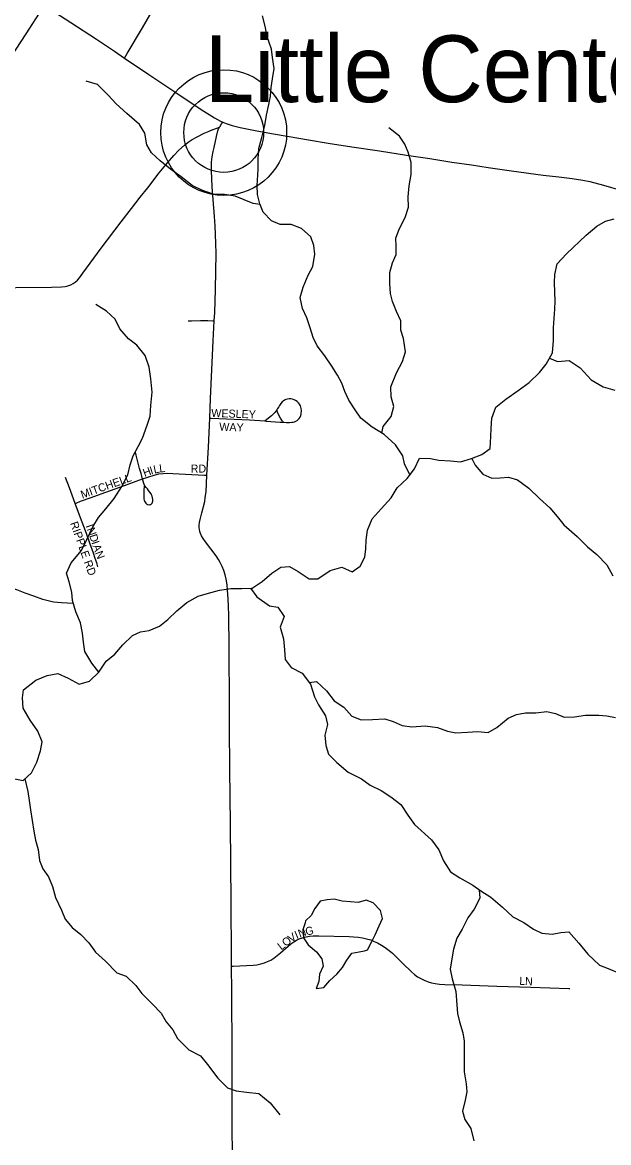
# Model space of a CAD drawing. Extents: x 1442749 to 1756758, y 235267 to 677782.
# Drawn here: x 1580655 to 1584314, y 536473 to 543469 of the extents above; entities that cross this region are included whole.
import ezdxf

# ---------------------------------------------------------------- set-up
doc = ezdxf.new("R2010")
doc.units = 0
for name, color, linetype in [('GM_X_County_Road', 7, 'Continuous'), ('GM_X_Major_River', 7, 'Continuous'), ('GM_X_Minor_Lake', 7, 'Continuous'), ('GM_X_Minor_River', 7, 'Continuous'), ('GM_X_Township_Road', 7, 'Continuous'), ('GM_X_Township_Subdivision', 7, 'Continuous'), ('GM_X_Township_Subdivision_Text', 7, 'Continuous'), ('GM_X_Unincorporated', 7, 'Continuous'), ('GM_X_Unincorporated_Location', 7, 'Continuous'), ('GM_X_Unincorporated_Text', 7, 'Continuous')]:
    doc.layers.add(name, color=color, linetype=linetype)

msp = doc.modelspace()

# ---------------------------------------------------------------- linework, layer by layer
at = {"layer": 'GM_X_County_Road'}
for points in [[(1580791.7, 543575.1), (1580957.8, 543468.8), (1581117.1, 543364.6), (1581228.7, 543289.4), (1581291.8, 543246.9)], [(1581291.8, 543246.9), (1581308.4, 543274.6), (1581404.2, 543435.1), (1581504.9, 543608)], [(1581291.8, 543246.9), (1581443.6, 543144.6), (1581607, 543034.9), (1581771, 542926), (1581854.2, 542874), (1581891.1, 542853.3), (1581905.4, 542846.9)], [(1581905.4, 542846.9), (1581926.5, 542837.5), (1581963.3, 542824.9), (1582013.8, 542812), (1582106.8, 542793.2), (1582210.2, 542775.2), (1582320.2, 542757.2), (1582439.8, 542736.8), (1582562.6, 542715.4), (1582711.6, 542692.3), (1582883.6, 542666.8), (1583052.4, 542640.8), (1583198.2, 542618.8), (1583334.3, 542597.3), (1583457.5, 542578.8), (1583561.3, 542563.4), (1583707.3, 542543.1), (1583905.2, 542515.7), (1584002.7, 542503.9), (1584087.3, 542495.1), (1584152.1, 542485), (1584197.1, 542475.4), (1584282.8, 542452.7), (1584396.1, 542419.2)]]:
    msp.add_lwpolyline(points, dxfattribs=at)
at = {"layer": 'GM_X_Major_River'}
msp.add_lwpolyline([(1580606.3, 538744.2), (1580658.3, 538735.1), (1580711.4, 538782.1), (1580744.9, 538849.7), (1580768.5, 538919.4), (1580777.8, 538975.4), (1580751.2, 539042.2), (1580702.6, 539111.5), (1580660.1, 539186.6), (1580655.5, 539251), (1580660.6, 539301), (1580738.1, 539361.6), (1580808.9, 539390.2), (1580875.3, 539402.9), (1580940.8, 539373.4), (1581008.1, 539335.9), (1581072.7, 539354.6), (1581132, 539411.5), (1581177.7, 539480.8), (1581230.7, 539523.8), (1581282.1, 539581), (1581341.5, 539639.9), (1581392.1, 539662.9), (1581446.4, 539671.8), (1581511.1, 539698.6), (1581562.1, 539739.7), (1581619.4, 539794.6), (1581680.7, 539845.5), (1581751.7, 539886.2), (1581816.3, 539904.9), (1581884.8, 539923.5), (1581955.2, 539934.1), (1582023.4, 539934.7), (1582089.5, 539935.3), (1582150.6, 539978.1), (1582211.8, 540029), (1582268.8, 540068), (1582321, 540070.9), (1582376.4, 540039.6), (1582445.5, 539994), (1582499.7, 539994.9), (1582574.9, 540045.5), (1582647.6, 540068), (1582713.1, 540038.5), (1582764, 540073.6), (1582791.2, 540129.2), (1582798.4, 540181.2), (1582799.6, 540235.4), (1582808.9, 540297.4), (1582838.6, 540369.1), (1582894.1, 540432.1), (1582955.7, 540499.1), (1582993.1, 540562.5), (1583056.5, 540621.4), (1583101.9, 540680.6), (1583133.5, 540748.2), (1583201.5, 540744.8), (1583253.5, 540735.7), (1583327.5, 540732.1), (1583389.5, 540724.8), (1583458.1, 540745.4), (1583522.8, 540770.1), (1583573.7, 540807.2), (1583579.4, 540883.3), (1583580.5, 540933.5), (1583585.9, 540997.6), (1583609.4, 541065.3), (1583672.7, 541116.2), (1583750, 541170.8), (1583817.2, 541219.5), (1583882.7, 541282.4), (1583924, 541335.7), (1583963.6, 541405.1), (1583969.3, 541483.3), (1583969, 541561.5), (1583974.3, 541619.6), (1583977.6, 541677.8), (1583980.7, 541727.9), (1583977.9, 541784.1), (1583975.2, 541844.4), (1583978.3, 541894.5), (1583993.8, 541962.4), (1584051.3, 542023.4), (1584174.1, 542141.3), (1584241.5, 542196), (1584294.2, 542227), (1584348.7, 542242)], dxfattribs=at)
at = {"layer": 'GM_X_Minor_Lake'}
for points in [[(1582789.4, 537671.6), (1582809.4, 537676), (1582836.1, 537729.8), (1582856.7, 537771.7), (1582881.4, 537827.5), (1582902, 537873.4), (1582890.6, 537923.7), (1582845, 537970.4), (1582801.1, 537986.9), (1582750.9, 537973.4), (1582702.8, 537976), (1582650.7, 537980.6), (1582600.8, 537993.2), (1582556.6, 537989.7), (1582514.4, 537980.2), (1582479.8, 537934.4), (1582457.2, 537890.6), (1582422.8, 537858.9), (1582418.7, 537845)], [(1582418.7, 537845), (1582406.1, 537802.9), (1582409.5, 537752.7), (1582439, 537708.3), (1582490.6, 537663.6), (1582524.2, 537621.1), (1582531.6, 537574.8), (1582509, 537525), (1582504.5, 537478.9), (1582487.9, 537435), (1582536.1, 537442.4), (1582574.7, 537486.1), (1582617.3, 537525.7), (1582653.8, 537567.4), (1582680.4, 537613.2), (1582711, 537657), (1582757.2, 537664.5), (1582789.4, 537671.6)]]:
    msp.add_lwpolyline(points, dxfattribs=at)
at = {"layer": 'GM_X_Minor_River'}
for points in [[(1583074, 540644.2), (1583040, 540711.7), (1583028.6, 540762), (1582983.3, 540830.7), (1582911.9, 540895.7), (1582838.3, 540940.7), (1582766.8, 540997.6), (1582731.4, 541050.2), (1582692, 541110.8), (1582666.6, 541163.3), (1582649.2, 541215.6), (1582621.7, 541266), (1582586.3, 541322.6), (1582543, 541387.3), (1582495.6, 541450), (1582470.2, 541502.4), (1582450.8, 541560.8), (1582429.5, 541623.2), (1582402.2, 541681.7), (1582389, 541752), (1582407.8, 541816), (1582438.7, 541889.9), (1582467.4, 541945.7), (1582480.4, 542021.8), (1582473, 542076), (1582455.6, 542130.3), (1582396.1, 542183.2), (1582332.3, 542207.9), (1582264.1, 542206.7), (1582210.3, 542229.4), (1582156.8, 542284.2), (1582137.4, 542336.5), (1582122, 542394.9), (1582120.7, 542451), (1582125.9, 542551.3), (1582126.7, 542615.4), (1582131.5, 542681.6), (1582148.3, 542749.6), (1582167.3, 542825.5), (1582178, 542889.6), (1582192.9, 542955.6), (1582203.5, 543009.7), (1582208.2, 543063.7), (1582216.8, 543117.8), (1582225.6, 543181.9), (1582216.4, 543250.2), (1582209, 543302.4), (1582179.9, 543384.9), (1582172.5, 543437.2), (1582153.4, 543509.6)], [(1582139.3, 542331.3), (1582095.3, 542339), (1581983.6, 542384.4), (1581915.6, 542395.2), (1581845.5, 542396), (1581775.6, 542420.9), (1581713.8, 542451.7), (1581646.3, 542504.6), (1581578.8, 542553.5), (1581515.2, 542604.4), (1581459.7, 542655.2), (1581432.3, 542705.6), (1581419.1, 542778), (1581385.7, 542832.5), (1581306.3, 542899.6), (1581238.9, 542960.5), (1581189.4, 543015.2), (1581124.1, 543082.2), (1581052.2, 543103)], [(1582898.4, 540903.9), (1582906.5, 540945.9), (1582957.3, 541007.5), (1582974.1, 541069.5), (1582956.8, 541129.8), (1582955.5, 541194), (1582990.7, 541279.9), (1583027.6, 541351.7), (1583046.3, 541411.6), (1583033.3, 541496), (1583015.9, 541546.3), (1583016.6, 541606.5), (1582989.2, 541662.9), (1582965.9, 541725.4), (1582952.5, 541775.7), (1582949.2, 541837.9), (1582948, 541908.1), (1582964.8, 541968.1), (1582987.4, 542020), (1582988.1, 542072.1), (1582986.6, 542122.2), (1583007.4, 542178.2), (1583044.3, 542251.9), (1583065.1, 542315.9), (1583061.9, 542380.1), (1583068.7, 542448.2), (1583081.6, 542520.2), (1583080.5, 542594.5), (1583063.2, 542658.8), (1583041.7, 542709.2), (1583008.3, 542759.8), (1582942.7, 542810.6)], [(1581131.4, 539410.9), (1581087, 539466.6), (1581043.8, 539541.3), (1581036.5, 539599.5), (1581029.2, 539655.8), (1581017.9, 539720.1), (1580988.7, 539788.6), (1580967.4, 539859.1), (1580962.1, 539911.3), (1580946.8, 539975.6), (1580929.4, 540030), (1580958.2, 540093.8), (1581023.3, 540171.3), (1581056.1, 540239.1), (1581095.2, 540318.9), (1581129.9, 540376.6), (1581174.7, 540430.3), (1581227.6, 540495.8), (1581274.6, 540571.5), (1581313.5, 540643.3), (1581328.3, 540705.3), (1581347, 540763.2), (1581377.7, 540821), (1581404.4, 540872.9), (1581433.5, 540954.8), (1581452.2, 541010.7), (1581457, 541076.8), (1581464, 541161), (1581456.9, 541243.3), (1581445.8, 541315.6), (1581420.6, 541388.1), (1581369.2, 541452.9), (1581317.6, 541493.6), (1581262.2, 541556.4), (1581232.9, 541614.9), (1581179.4, 541665.6), (1581113.7, 541708.5)], [(1583944.8, 541372.2), (1583995.6, 541350.6), (1584067.9, 541357.8), (1584135.5, 541310.9), (1584204.7, 541237.9), (1584280.4, 541192.9), (1584352.3, 541172)], [(1583460.4, 540746.3), (1583480.9, 540704.7), (1583528.3, 540648), (1583584.1, 540623.3), (1583636.2, 540624.7), (1583688.4, 540628.1), (1583744.3, 540613.4), (1583815.9, 540560.4), (1583883.2, 540495.5), (1583946.7, 540436.6), (1583992.1, 540383.9), (1584033.6, 540331.3), (1584116.9, 540258.2), (1584182.3, 540193.2), (1584239.8, 540146.4), (1584303.2, 540081.5), (1584340.5, 540012.9)], [(1580973, 539840.7), (1580899.1, 539843.8), (1580849.1, 539848.4), (1580783.1, 539865.2), (1580725.2, 539885.9), (1580671.4, 539904.6), (1580619.5, 539925.2), (1580553.6, 539948), (1580486.2, 540011), (1580464.8, 540061.4), (1580384.1, 540168)], [(1582078.7, 539935.2), (1582118.2, 539882), (1582197.7, 539824.9), (1582249.7, 539816.3), (1582289.1, 539759.7), (1582264.2, 539691.8), (1582285.4, 539619.3), (1582290.6, 539551.1), (1582293.9, 539490.9), (1582331.4, 539440.3), (1582401.1, 539405.4), (1582452.4, 539336.6), (1582477.5, 539258.1), (1582503, 539207.7), (1582546.3, 539139), (1582559.7, 539084.7), (1582542.8, 539016.7), (1582548, 538952.5), (1582565.4, 538898.1), (1582616.9, 538847.4), (1582688.4, 538786.4), (1582772.1, 538745.3), (1582825.7, 538704.6), (1582893.5, 538671.8), (1582955.1, 538632.9), (1583016.7, 538584.1), (1583060, 538517.4), (1583101.4, 538460.8), (1583208.5, 538363.3), (1583253.8, 538302.6), (1583283.1, 538232.1), (1583326.3, 538163.4), (1583386, 538126.6), (1583465.7, 538081.6), (1583517.3, 538044.9), (1583579, 538006.1), (1583652.4, 537943.1), (1583715.8, 537882.2), (1583785.6, 537847.3), (1583845.2, 537806.5), (1583897, 537781.8), (1583961.1, 537775.1), (1584015.3, 537784.5), (1584065.5, 537789.9), (1584128.8, 537719), (1584184.1, 537650.2), (1584257.4, 537581.1), (1584311.3, 537560.5), (1584379.1, 537531.6)], [(1582444.8, 539346.9), (1582490.7, 539352.2), (1582552.1, 539295.4), (1582601.5, 539232.7), (1582661.1, 539191.9), (1582710.6, 539137.1), (1582768.4, 539114.4), (1582840.6, 539115.6), (1582916.8, 539120.7), (1582968.7, 539104.1), (1583024.6, 539077.4), (1583086.6, 539070.7), (1583168.8, 539075.7), (1583244.9, 539064.8), (1583308.7, 539042), (1583360.7, 539031.4), (1583432.9, 539036.6), (1583495.1, 539039.9), (1583561.2, 539035.1), (1583615.7, 539064.6), (1583686.5, 539123.9), (1583738.9, 539147.4), (1583795.1, 539156.8), (1583859.3, 539158.1), (1583927.5, 539165.3), (1583981.5, 539152.7), (1584037.3, 539129.9), (1584101.5, 539131.2), (1584169.8, 539142.5), (1584252, 539143.5), (1584302, 539138.9), (1584356, 539128.3)], [(1580669.6, 538745.2), (1580688.7, 538666.9), (1580696, 538608.7), (1580705.3, 538550.4), (1580725.8, 538417.8), (1580737.2, 538361.5), (1580752.5, 538303.2), (1580761.7, 538234.9), (1580783.1, 538182.5), (1580816.6, 538132), (1580842, 538073.5), (1580861.2, 538003.1), (1580898.3, 537924.5), (1580921.7, 537868.1), (1580965.2, 537817.4), (1581018.8, 537772.7), (1581068.3, 537720), (1581111.7, 537663.3), (1581173.1, 537606.5), (1581244.4, 537533.4), (1581302.3, 537512.7), (1581361.7, 537453.9), (1581399.2, 537403.3), (1581466.6, 537338.4), (1581520, 537281.6), (1581551.4, 537227.1), (1581592.9, 537176.5), (1581622.4, 537124), (1581693.7, 537053), (1581765.4, 537014), (1581810.8, 536961.4), (1581874, 536876.4), (1581935.4, 536815.5), (1581989.2, 536796.9), (1582053.3, 536788.1), (1582131.3, 536779.2), (1582200.8, 536722.3), (1582262.1, 536647.3)], [(1583506.3, 538052.7), (1583510.8, 537998.8), (1583473.9, 537931.1), (1583435.2, 537877.4), (1583400.2, 537805.6), (1583365.5, 537749.8), (1583344.7, 537681.9), (1583335.9, 537619.8), (1583325.1, 537555.7), (1583338.4, 537495.4), (1583359.5, 537416.9), (1583366.6, 537332.6), (1583369.9, 537280.4), (1583383.4, 537228.2), (1583404.6, 537157.7), (1583412, 537107.5), (1583413.3, 537047.3), (1583411.7, 536914.9), (1583424.8, 536840.6), (1583428.2, 536790.4), (1583417.6, 536738.4), (1583402.7, 536668.4), (1583416.2, 536618.1), (1583453.6, 536561.5), (1583472.7, 536485.1)]]:
    msp.add_lwpolyline(points, dxfattribs=at)
at = {"layer": 'GM_X_Township_Road'}
for points in [[(1581884.9, 542815.7), (1581886, 542817.8), (1581898.2, 542836), (1581905.4, 542846.9)], [(1580390.5, 541812.3), (1580836, 541816.7), (1580898.2, 541817.7), (1580920.6, 541819.7), (1580939.2, 541823.7), (1580956.9, 541830.4), (1580970.8, 541837.7), (1580983.7, 541846.8), (1580997.9, 541859.6), (1581010.7, 541873.9), (1581031.9, 541902.7), (1581146.1, 542059.2), (1581271.7, 542223.4), (1581335.1, 542307.1), (1581389.4, 542377.1), (1581436.8, 542435.7), (1581508.7, 542529.3), (1581560.5, 542593.2), (1581599.6, 542637.8), (1581631.7, 542670.9), (1581665.7, 542702.1), (1581689.1, 542720.6), (1581713.8, 542737.3), (1581745.3, 542755.5), (1581789.7, 542777.7), (1581819.9, 542790.9), (1581829.3, 542794.5), (1581884.9, 542815.7)], [(1581852.6, 541606.2), (1581855.3, 541657.8), (1581860.9, 541801.8), (1581863.5, 542028.3), (1581862.1, 542086.4), (1581859.5, 542147.4), (1581856.9, 542198.3), (1581853.2, 542257.5), (1581840, 542443.3), (1581834.8, 542544.5), (1581834.4, 542566.9), (1581835.5, 542596.3), (1581837.4, 542612.1), (1581840, 542629), (1581846.1, 542662.9), (1581850.7, 542687.7), (1581866.1, 542757.1), (1581873.9, 542791.3), (1581878.6, 542803.9), (1581884.9, 542815.7)], [(1581823.9, 540998), (1581829.7, 541121.1), (1581846, 541481.4), (1581852.6, 541606.2)], [(1581806.4, 540641.9), (1581815.3, 540816.5), (1581823.9, 540998)], [(1581960.9, 537574.5), (1581960.6, 537635.5), (1581956.9, 537973.3), (1581953.9, 538461.6), (1581949, 538805.8), (1581946.7, 539067.4), (1581946.7, 539198.3), (1581945.5, 539565.7), (1581942.9, 539767.3), (1581941.2, 539822.2), (1581939.7, 539869.5), (1581935.1, 539923.4), (1581931.8, 539956.4), (1581926.6, 539992.2), (1581919.9, 540019), (1581911.6, 540046.5), (1581901.6, 540070.4), (1581890.1, 540095.1), (1581879.2, 540115.2), (1581864.9, 540137.5), (1581797.1, 540225.9), (1581782.5, 540245.4), (1581772.4, 540263.2), (1581766.8, 540276.9), (1581762.2, 540289.7), (1581759.7, 540302.3), (1581758.1, 540314.3), (1581758.1, 540330.3), (1581760.2, 540346.6), (1581764.5, 540363.9), (1581775.3, 540405.6), (1581792.5, 540476.2), (1581796.4, 540502.1), (1581801.2, 540538.3), (1581806.4, 540641.9)], [(1581968.5, 536278), (1581964.2, 536553.2), (1581964.4, 536740.1), (1581964.5, 536871.3), (1581963.6, 537028.7), (1581961.8, 537415.8), (1581960.9, 537574.5)]]:
    msp.add_lwpolyline(points, dxfattribs=at)
at = {"layer": 'GM_X_Township_Subdivision'}
for points in [[(1580390.5, 541812.3), (1580388.2, 541950.7), (1580385.3, 542163.7), (1580384.3, 542275.3), (1580382.2, 542386.7), (1580380.1, 542563.8), (1580377.5, 542744), (1580379.5, 542780.1), (1580383.7, 542821.8), (1580390.8, 542866.8), (1580400.8, 542911.3), (1580411.4, 542948.9), (1580422.5, 542979.4), (1580438.3, 543015.1), (1580460.4, 543058.7), (1580486.3, 543104.1), (1580521.8, 543159), (1580678.6, 543397.1), (1580779.7, 543556.4), (1580791.7, 543575.1)], [(1581688.9, 541605.7), (1581711.1, 541606.2), (1581765.9, 541607.5), (1581812.4, 541606.8), (1581843, 541606.4), (1581852.6, 541606.2)], [(1582284, 540972), (1582303.2, 540971.3), (1582322.6, 540971.3), (1582335.5, 540971.7), (1582345.4, 540972.8), (1582353.9, 540974.9), (1582362.3, 540978), (1582369.9, 540983.4), (1582376.3, 540988.8), (1582381.9, 540994.7), (1582388.3, 541003.9), (1582392.5, 541014.6), (1582395, 541025.6), (1582396.8, 541045), (1582395.4, 541058.1), (1582392.9, 541066.7), (1582390.1, 541074.1), (1582384, 541084.7), (1582377.6, 541093.6), (1582368.8, 541101.3), (1582359.6, 541108.1), (1582350.4, 541112.7), (1582339.8, 541116.5), (1582329.5, 541118.4), (1582319.1, 541118.7), (1582308.5, 541117), (1582298.4, 541113.6), (1582290.8, 541109.9), (1582283, 541104.1), (1582276.7, 541098.6), (1582268.5, 541089), (1582260.5, 541077.7), (1582254.4, 541068.4), (1582247.6, 541057.8), (1582242.9, 541049.7)], [(1582242.9, 541049.7), (1582236.3, 541040.7), (1582231, 541033.8), (1582220.3, 541022.7), (1582209.1, 541012.5), (1582169.2, 540981.7), (1582167.4, 540980.3)], [(1582284, 540972), (1582279, 540977), (1582273.7, 540984.1), (1582265.4, 540998.2), (1582255.8, 541015.5), (1582247.1, 541034.7), (1582242.9, 541049.7)], [(1581823.9, 540998), (1581832.1, 540997.6), (1582071.3, 540986.3), (1582167.4, 540980.3), (1582176.3, 540979.7), (1582264.3, 540972.3), (1582284, 540972)], [(1581405.1, 540617.8), (1581395.6, 540651.7), (1581386.4, 540683.4), (1581374.7, 540724.8), (1581364.2, 540766.4), (1581360.1, 540785.4)], [(1580984.1, 540464.8), (1580965.8, 540515.7), (1580948.4, 540562.4), (1580923.8, 540627.3)], [(1580984.1, 540464.8), (1580990, 540467.2), (1581016.4, 540478.2), (1581083.5, 540502.9), (1581147.1, 540525.8), (1581291.9, 540577.1), (1581405.1, 540617.8)], [(1581405.1, 540617.8), (1581431.7, 540627.4), (1581484, 540644.2), (1581506.8, 540649), (1581533.6, 540652), (1581562.9, 540653.2), (1581593.5, 540652.3), (1581792.2, 540642.6), (1581806.4, 540641.9)], [(1581416.1, 540577.8), (1581415.5, 540569.8), (1581413.6, 540547.8), (1581412.3, 540515.1), (1581412.6, 540505.9), (1581413.6, 540494.1), (1581414.9, 540485.7), (1581416.9, 540478.7), (1581420, 540472.3), (1581424.5, 540466.6), (1581429, 540462.4), (1581433.7, 540459.3), (1581438.4, 540457.4), (1581445.6, 540456.5), (1581451.7, 540457.6), (1581456.4, 540459.3), (1581461.1, 540463.1), (1581464.4, 540467.7), (1581467.2, 540473.2), (1581468.5, 540480), (1581468.7, 540490), (1581467.3, 540499.7), (1581463.7, 540511.3), (1581460.4, 540518.6), (1581457.5, 540524), (1581449.5, 540536.4), (1581442.4, 540546.6), (1581434.6, 540556.2), (1581426.8, 540565.5), (1581418.9, 540574.1), (1581417.9, 540575.7), (1581416.4, 540578.2), (1581413, 540589.2), (1581405.1, 540617.8)], [(1581125.7, 540068.7), (1581118.3, 540093.7), (1581109.8, 540120.7), (1581098.3, 540154.7), (1581076.2, 540217.1), (1581054.5, 540277.5), (1581011.5, 540391.9), (1580984.1, 540464.8)], [(1581960.9, 537574.5), (1581969.7, 537575), (1582095, 537581.4), (1582118, 537584.1), (1582142.7, 537589.4), (1582166.8, 537595.8), (1582185.3, 537604.1), (1582204.5, 537613.4), (1582224.8, 537625.6), (1582265.5, 537657.5), (1582329.9, 537714), (1582348.3, 537726.5), (1582366.5, 537737.3), (1582381.5, 537744.8), (1582403.6, 537752.7), (1582425.1, 537758.4), (1582445.9, 537762), (1582470.6, 537764.3), (1582505.6, 537765.1), (1582695.1, 537760.3), (1582721.1, 537759.1), (1582751, 537756.5), (1582778.2, 537752.2), (1582802.4, 537746.7), (1582829.5, 537738.6), (1582851.2, 537729.8), (1582871.4, 537720.7), (1582895.5, 537706.9), (1582919.5, 537690.8), (1582944.2, 537673.2), (1582964.6, 537656), (1583029.7, 537590.8), (1583083.7, 537538.8), (1583102.3, 537522.3), (1583121.2, 537509.3), (1583142, 537497.5), (1583167.4, 537485.2), (1583188.2, 537477.4), (1583207.7, 537471.5), (1583231.2, 537466.3), (1583257.8, 537463.1), (1583292.3, 537461.1), (1583399.3, 537457.4), (1583615.6, 537450.1), (1583828.6, 537443.7), (1584064.7, 537435.4), (1584071.3, 537435)]]:
    msp.add_lwpolyline(points, dxfattribs=at)
at = {"layer": 'GM_X_Unincorporated'}
for radius in [392.8, 249]:
    msp.add_circle((1581911.4, 542781.2), radius, dxfattribs=at)
at = {"layer": 'GM_X_Unincorporated_Location'}
msp.add_line((1581911.4, 542781.2), (1581911.4, 542781.2), dxfattribs=at)

# ---------------------------------------------------------------- texts
at = {"layer": 'GM_X_Township_Subdivision_Text'}
for s, rotation, p in [('WESLEY', 357.95571, (1581832.7, 541005.4)), ('WAY', 358.2651, (1581882.9, 540919.4)), ('H', 20.45371, (1581417.7, 540629.8)), ('I', 17.12201, (1581458.2, 540644.9)), ('L', 11.77609, (1581478, 540651.1)), ('L', 5.80028, (1581511.1, 540658.1)), ('RD', 0.00001, (1581704.8, 540657.7)), ('MITCHELL', 19.70988, (1581028.6, 540494.5)), ('RIPPLE RD', 289.70988, (1580951.4, 540341.4)), ('I', 288.91875, (1581049.1, 540325.7)), ('N', 288.89807, (1581056.2, 540304.9)), ('D', 288.89807, (1581070.5, 540263.3)), ('I', 288.93661, (1581084.8, 540221.6)), ('A', 289.33199, (1581092, 540200.4)), ('N', 291.35752, (1581107.3, 540157.1)), ('N', 19.3406, (1582385.9, 537752.7)), ('G', 10.23839, (1582425.4, 537766.7)), ('O', 37.69859, (1582298.6, 537693.8)), ('V', 34.90249, (1582332.9, 537720.4)), ('I', 23.47416, (1582366.6, 537744.3)), ('L', 37.69522, (1582270.7, 537672.3)), ('L', 356.72016, (1583755.7, 537458.9)), ('N', 357.13521, (1583791.3, 537456.9))]:
    msp.add_text(s, height=50, rotation=rotation, dxfattribs=at).set_placement(p)
at = {"layer": 'GM_X_Unincorporated_Text'}
msp.add_text('Little Center', height=417, rotation=0.00001, dxfattribs=at).set_placement((1581792.8, 542971.3))

doc.saveas('drawing.dxf')
